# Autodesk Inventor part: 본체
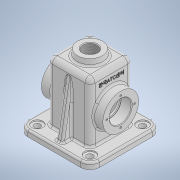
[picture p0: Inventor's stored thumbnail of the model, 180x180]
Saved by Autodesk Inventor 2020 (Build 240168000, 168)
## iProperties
Created: 2021-07
Part Number: 본체
Material: 일반
Document SubType Name: Modeling
Designer: Owner
Density: 1 g/cm^3
Appearance: 기본값
Mass: 278.261 g
Surface Area: 858.222 cm^2
Volume: 278.261 cm^3
Author: Owner
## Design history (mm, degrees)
sketch "스케치1"
  geometry: L1 (34, -34)-(-34, -34); L2 (-34, -34)-(-34, 34); L3 (-34, 34)-(34, 34); L4 (34, 34)-(34, -34); L5 (34, -34)-(-34, 34); L6 (-34, -34)-(34, 34); 1 further point
  constraints: 12 end point, 2 midpoint, 2 parallel, 1 horizontal, 1 perpendicular
  dimensions: "d0" = 68 distance of L2.end L3.end; "d1" = 68 distance of L1.end L2.end
extrude "돌출1" new body sketch "스케치1" distance "d2" = 105; taper "d3" = 0 deg
fillet "모깎기1" dims "d4" = 8
feature "쉘1" dims "d5" = 5
node "작업 평면1"
sketch "스케치2"
  geometry: C1 r 20 at (0, 0); 1 further point
  constraints: 1 centre point, 1 coincident
  dimensions: "d7" = 40 diameter of C1
extrude "돌출2" join sketch "스케치2" stored distance "d8" = 105; taper "d9" = 8 deg
sketch "스케치3"
  geometry: L1 (57, 57)-(-57, 57); L2 (-57, 57)-(-57, -57); L3 (-57, -57)-(57, -57); L4 (57, -57)-(57, 57); L5 (57, 57)-(-57, -57); L6 (-57, 57)-(57, -57); 1 further point
  constraints: 12 end point, 2 midpoint, 2 parallel, 1 horizontal, 1 perpendicular
  dimensions: "d10" = 114 distance of L3.end L2.end; "d11" = 114 distance of L1.end L2.end
extrude "돌출3" join sketch "스케치3" distance "d12" = 10; taper "d13" = 0 deg
fillet "모깎기2" dims "d14" = 15
sketch "스케치4"
  geometry: A1 r 15 centre (-42, -42) between (-57, -42) and (-42, -57) reference; 2 further points
  constraints: 1 coincident
hole "구멍1" sketch "스케치4" at (-42, -42) diameter "d15" = 10; stored, may be unused: countersink angle "d19" = 90 deg, drill point angle "d21" = 0 deg; dims "d16" = 8, "d17" = 18, "d18" = 2, "d20" = 20
fillet "모깎기3" dims "d25" = 8
sketch "스케치5"
  geometry: C1 r 20 at (0, 0) reference; 2 further points
  constraints: 1 coincident
hole "구멍2" sketch "스케치5" at (0, 0) diameter "d26" = 22.83494; stored, may be unused: countersink angle "d30" = 90 deg, drill point angle "d32" = 0 deg; dims "d27" = 50, "d28" = 18, "d29" = 2, "d31" = 59.3
node "작업 평면2"
sketch "스케치6"
  geometry: L1 (0, 42)-(0, -42) reference; C1 r 28.5 at (52, 0); 2 further points
  constraints: 1 centre point, 1 horizontal alignment, 1 midpoint
  dimensions: "d34" = 57 diameter of C1; "d35" = 52 distance from line of L1 C1.centre
extrude "돌출4" join sketch "스케치6" stored distance "d36" = 10; taper "d37" = 0 deg
sketch "스케치7"
  geometry: C1 r 28.5 at (0, 0) reference; 2 further points
  constraints: 1 coincident
hole "구멍3" sketch "스케치7" at (0, 0) diameter "d38" = 30; stored, may be unused: countersink angle "d42" = 82 deg, drill point angle "d44" = 0 deg; dims "d39" = 50, "d40" = 35, "d41" = 17, "d43" = 20
sketch "스케치8" dims "d45" = 44
  geometry: C1 r 28.5 at (0, 0) reference; 3 further points
  constraints: 2 vertical alignment, 1 coincident, 2 other
hole "구멍4" sketch "스케치8" at (0, 22) diameter "d46" = 3.242; stored, may be unused: countersink angle "d50" = 82 deg, drill point angle "d52" = 118 deg; dims "d47" = 8, "d48" = 35, "d49" = 17, "d51" = 10
sketch "스케치9"
  geometry: L1 (10, 57)-(10, 42) reference; L2 (10, 49)-(38.066, 44.051); L3 (10, 57)-(0, 57) reference; 1 further point
  constraints: 2 end point, 1 point on line
  dimensions: "d56" = 8 distance from line of L2.start L3; "d57" = 10 deg angle of L3 L2
feature "리브1" sketch "스케치9" dims "d58" = 1, "d59" = 10, "d60" = 0, "d61" = 0, "d62" = 1, "d63" = 1
sketch "스케치10"
  geometry: L1 (29, 29)-(-29, 29); L2 (-29, 29)-(-29, -29); L3 (-29, -29)-(29, -29); L4 (29, -29)-(29, 29); L5 (29, 29)-(-29, -29); L6 (-29, 29)-(29, -29); 1 further point
  constraints: 12 end point, 2 midpoint, 2 parallel, 1 horizontal, 1 perpendicular
  dimensions: "d64" = 58 distance of L3.end L2.end; "d65" = 58 distance of L2.end L1.end
extrude "돌출5" cut sketch "스케치10" distance "d66" = 51.5; taper "d67" = 0 deg
fillet "모깎기4" dims "d68" = 3
fillet "모깎기5" dims "d69" = 3
sketch "스케치11"
  geometry: L1 (6, 18)-(46, 18) reference; L2 (-16, -97)-(68, -97) reference; 3 further points
  constraints: 1 midpoint, 1 vertical alignment, 1 other
  dimensions: "d70" = 25 distance from line of L1 point (26, -7)
feature "엠보싱1" sketch "스케치11" dims "d71" = 0.5, "d72" = 0
fillet "모깎기6" dims "d73" = 3
fillet "모깎기7" dims "d74" = 3
chamfer "모따기1" distance "d75" = 1; stored, may be unused: second distance "d76" = 2, angle "d77" = 45 deg
chamfer "모따기2" distance "d78" = 1; stored, may be unused: second distance "d79" = 2, angle "d80" = 45 deg
fillet "모깎기8" dims "d81" = 3
fillet "모깎기10" dims "d83" = 3
fillet "모깎기11" dims "d84" = 3
fillet "모깎기12" dims "d85" = 0.3
fillet "모깎기13" dims "d86" = 0.3
node "솔리드1"
pattern_circular "원형 패턴1" dims angle "d23" = 360 deg
pattern_circular "원형 패턴2" dims angle "d54" = 360 deg
mirror "미러1"
mirror "미러2"
feature "A9D066F2-1C7D-4E18-AEED-F7BC21143FA4" dims "d15" = 10, "d16" = 8, "d17" = 18, "d18" = 2, "d19" = 90 deg, "d20" = 20, "d21" = 0
other parameters: "d6" = -115, "d33" = 49
